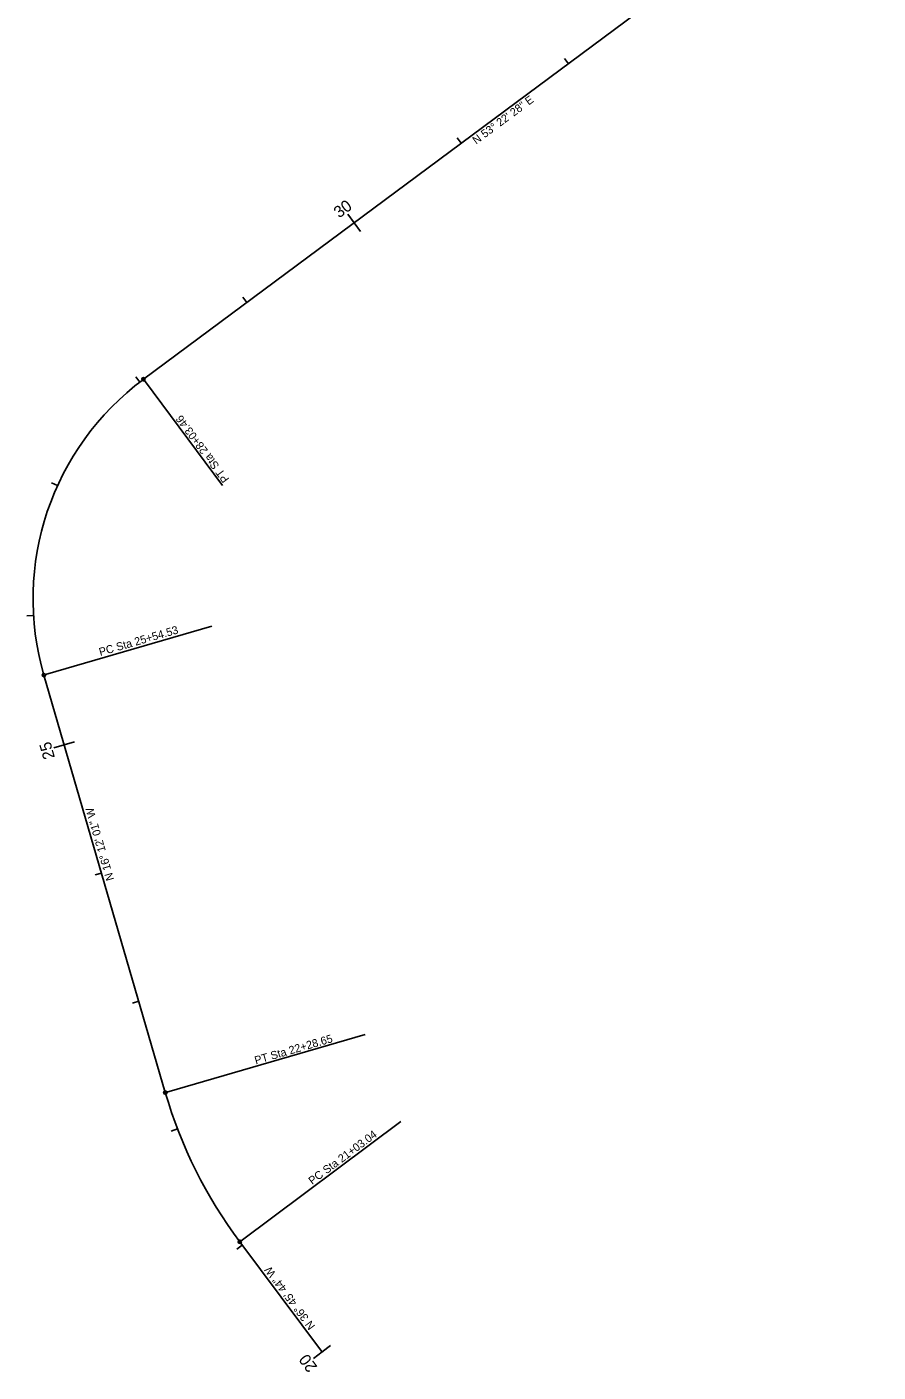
# Model space of a CAD drawing. Extents: x 1612377 to 1619444, y 1093143 to 1096386.
# Drawn here: x 1612377 to 1613015, y 1094184 to 1095192 of the extents above; entities that cross this region are included whole.
import ezdxf

# ---------------------------------------------------------------- set-up
doc = ezdxf.new("R2010")
doc.units = 0
for name, color, linetype in [('RD_GPK_Profile_Cell', 7, 'Continuous'), ('RD_HC_TX_Sta50', 7, 'Continuous'), ('RD_HY_Area_SS', 7, 'Continuous'), ('RD_PD_DR_Ditch', 7, 'Continuous'), ('RD_TX_Drainage', 7, 'Continuous')]:
    doc.layers.add(name, color=color, linetype=linetype)

msp = doc.modelspace()

# ---------------------------------------------------------------- linework, layer by layer
at = {"layer": 'RD_HC_TX_Sta50'}
for p, q in [((1612464.4, 1094928), (1613014.6, 1095337)), ((1612480.8, 1094393.3), (1612389.9, 1094706.2)), ((1612598.4, 1094198.6), (1612536.5, 1094281.5))]:
    msp.add_line(p, q, dxfattribs=at)
for centre, radius, start, end in [((1612586.7, 1094763.4), 205, 126.6256, 196.2003), ((1612816.9, 1094491), 350, 196.2003, 216.7623)]:
    msp.add_arc(centre, radius, start, end, dxfattribs=at)
at = {"layer": 'RD_HY_Area_SS'}
for p, q in [((1612465.2, 1094927), (1612523.6, 1094848.4)), ((1612391.1, 1094706.6), (1612515.6, 1094742.8)), ((1612482, 1094393.7), (1612630.4, 1094436.8)), ((1612537.5, 1094282.2), (1612657.3, 1094371.7))]:
    msp.add_line(p, q, dxfattribs=at)
for centre in [(1612464.4, 1094928), (1612389.9, 1094706.2), (1612480.8, 1094393.3), (1612536.5, 1094281.5)]:
    msp.add_circle(centre, 1.25, dxfattribs=at)
at = {"layer": 'RD_TX_Drainage'}
for p, q in [((1612782.7, 1095164.5), (1612779.7, 1095168.5)), ((1612702.4, 1095104.9), (1612699.4, 1095108.9)), ((1612622.2, 1095045.2), (1612617.4, 1095051.6)), ((1612622.2, 1095045.2), (1612626.9, 1095038.8)), ((1612541.9, 1094985.6), (1612538.9, 1094989.6)), ((1612461.7, 1094925.9), (1612458.6, 1094929.8)), ((1612400.1, 1094848.3), (1612395.6, 1094850.4)), ((1612382.1, 1094751), (1612377.1, 1094750.7)), ((1612405.1, 1094653.9), (1612397.4, 1094651.6)), ((1612405.1, 1094653.9), (1612412.8, 1094656.1)), ((1612433, 1094557.9), (1612428.2, 1094556.5)), ((1612460.9, 1094461.8), (1612456.1, 1094460.4)), ((1612489.9, 1094366.2), (1612485.2, 1094364.4)), ((1612538.3, 1094279), (1612534.3, 1094276)), ((1612598.2, 1094198.9), (1612591.8, 1094194.1)), ((1612598.2, 1094198.9), (1612604.6, 1094203.7))]:
    msp.add_line(p, q, dxfattribs=at)

# ---------------------------------------------------------------- texts
at = {"layer": 'RD_GPK_Profile_Cell'}
for s, rotation, p in [('N 53%%d 22\' 28" E', 36.6256, (1612713.6, 1095103.8)), ('N 16%%d 12\' 01" W', 106.2003, (1612442.5, 1094553.1)), ('N 36%%d 45\' 44" W', 126.7623, (1612593.3, 1094218.3))]:
    msp.add_text(s, height=6, rotation=rotation, dxfattribs=at).set_placement(p)
at = {"layer": 'RD_HY_Area_SS'}
for s, rotation, p in [('PT Sta 28+03.46', 126.6256, (1612529, 1094853.2)), ('PC Sta 25+54.53', 16.2003, (1612432.1, 1094720.5)), ('PT Sta 22+28.65', 16.2003, (1612548.6, 1094414.4)), ('PC Sta 21+03.04', 36.7623, (1612590.8, 1094324))]:
    msp.add_text(s, height=6, rotation=rotation, dxfattribs=at).set_placement(p)
at = {"layer": 'RD_PD_DR_Ditch'}
for s, rotation, p in [('30', 36.6256, (1612611, 1095048.4)), ('25', 106.2003, (1612398.2, 1094644.5)), ('20', 126.7623, (1612595, 1094187.8))]:
    msp.add_text(s, height=8.75, rotation=rotation, dxfattribs=at).set_placement(p)

doc.saveas('drawing.dxf')
